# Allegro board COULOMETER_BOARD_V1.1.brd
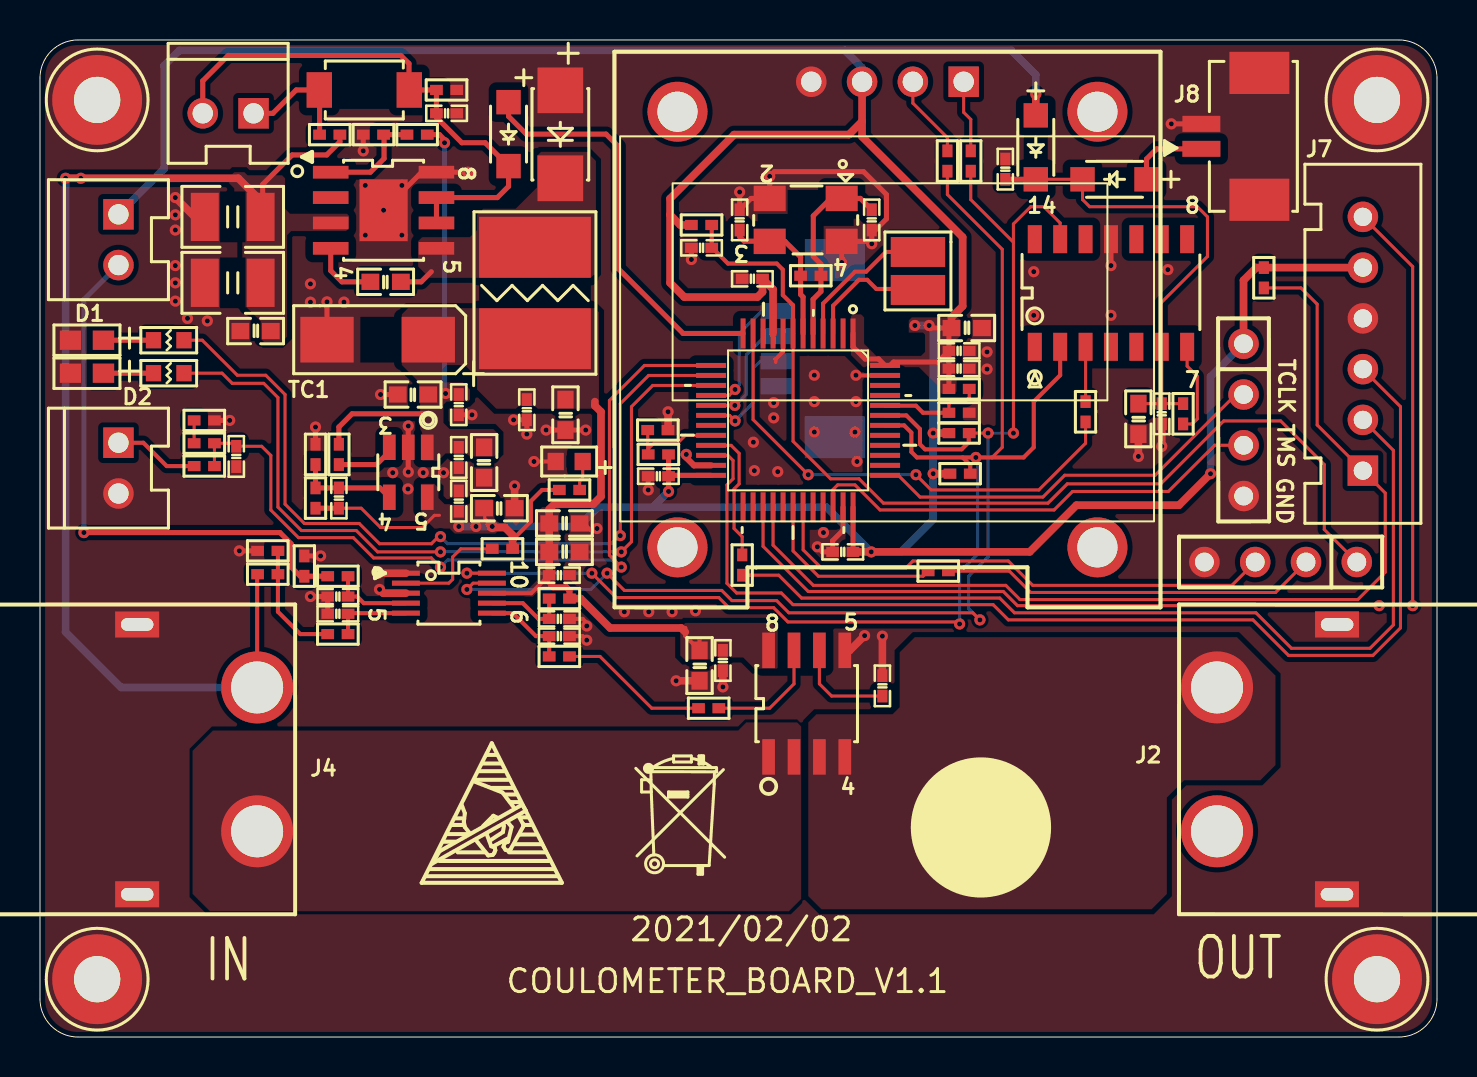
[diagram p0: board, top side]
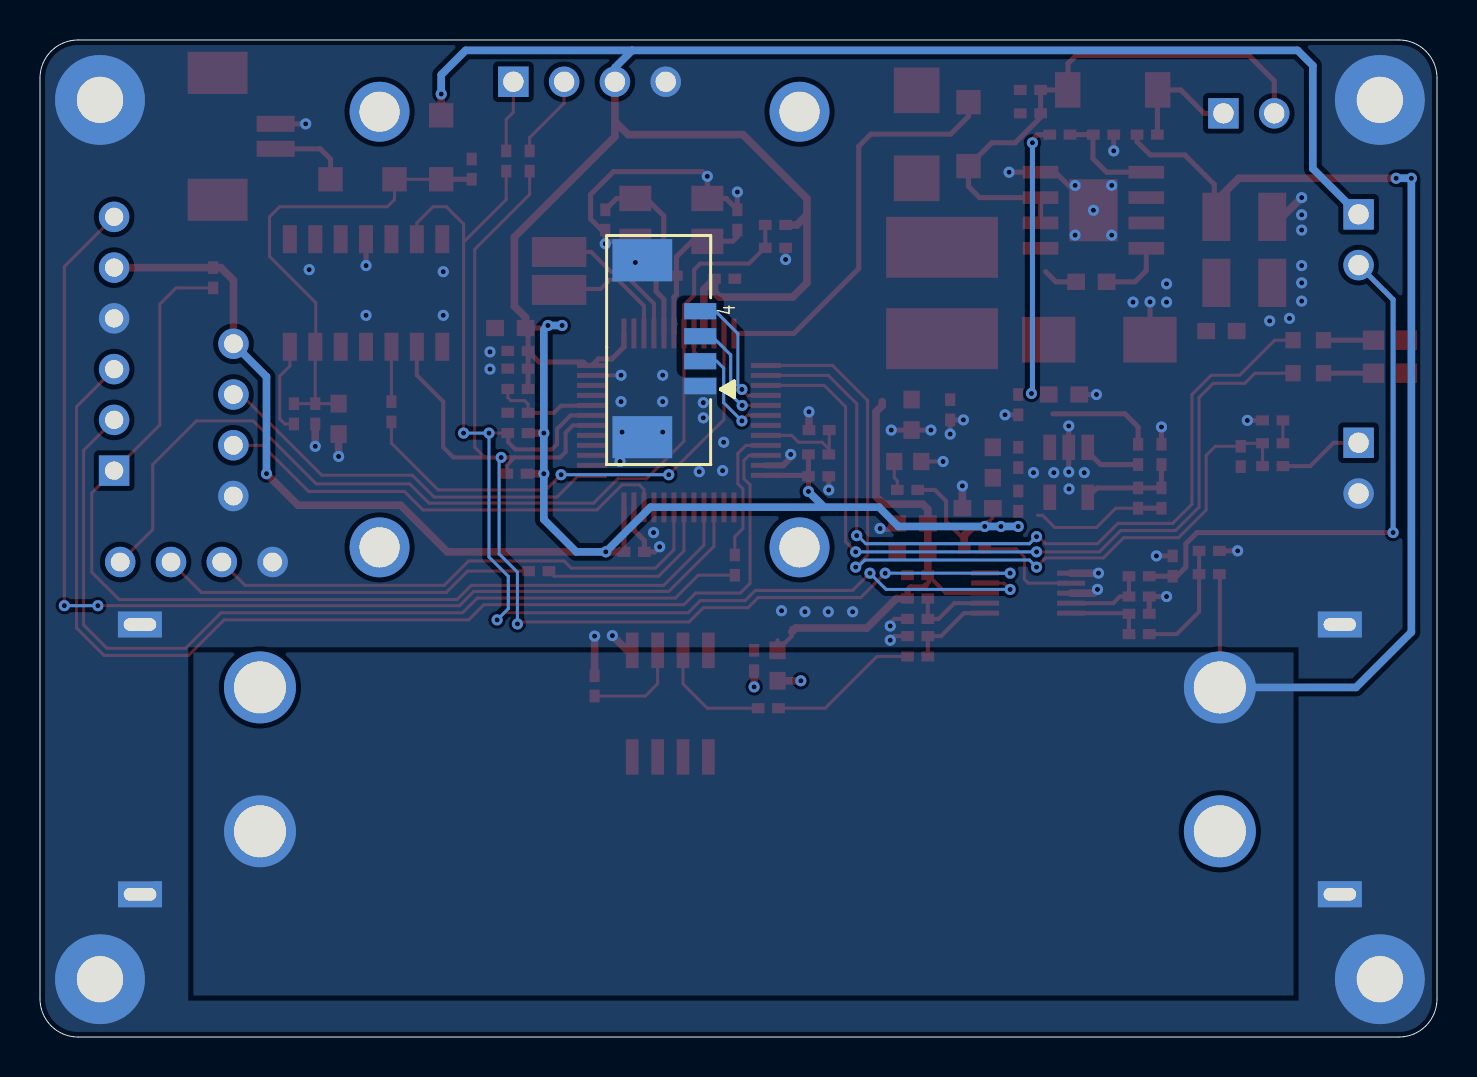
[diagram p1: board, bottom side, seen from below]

Outline 69.86 x 49.89 mm; copper layers: TOP, BOTTOM. Coordinates in mm from the lower left corner of the outline.
Outline path: 0,47.99 0,1.91 arc(0.56,0.56) 1.91,0 67.95,0 arc(69.3,0.56) 69.86,1.91 69.86,47.99 arc(69.3,49.34) 67.95,49.89 1.91,49.89 arc(0.56,49.34) 0,47.99

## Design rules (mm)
constraint set DEFAULT: min track width 0.152

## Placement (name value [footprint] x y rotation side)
C1  0.1uF/16V  [C0402]  33.08 39.49 180 top
C4  18pF/50V  [C0402]  34.99 40.89 270 top
C5  18pF/50V  [C0402]  41.59 40.89 90 top
C11  0.1uF/16V  [C0402]  35.62 37.94 180 top
C15  10uF/10V  [C0603]  46.34 35.48 180 top
C16  0.1uF/16V  [C0402]  40.14 24.28 180 top
C17  0.1uF/16V  [C0402]  45.96 34.34 0 top
C18  0.1uF/16V  [C0402]  45.96 33.45 0 top
C19  0.1uF/16V  [C0402]  30.92 28.06 180 top
C21  2.2uF/100V  [C1210]  9.64 41.04 0 top
C22  2.2uF/100V  [C1210]  9.64 37.74 0 top
C23  0.1uF/100V  [C0603]  10.78 35.33 180 top
C24  0.1uF/100V  [C0603]  17.28 37.79 0 top
C25  0.1uF/16V  [C0402]  20.94 31.64 270 top
C27  10uF/10V  [C0603]  18.65 32.15 0 top
C28  10uF/10V  [C0603]  26.27 31.14 90 top
C29  0.1uF/16V  [C0402]  24.34 31.39 270 top
C35  0.1uF/16V  [C0402]  20.33 46.22 0 top
C36  0.1uF/50V  [C0402]  34.15 18.84 270 top
C37  10uF/16V  [C0603]  32.98 18.59 90 top
C38  0.1uF/50V  [C0402]  42.12 17.57 90 top
C39  0.1uF/50V  [C0402]  25.97 23.11 0 top
C40  10uF/16V  [C0603]  26.22 25.7 180 top
C41  10uF/16V  [C0603]  26.22 24.28 180 top
C42  1nF/50V  [C0402]  14.9 21.18 180 top
C43  1nF/50V  [C0402]  14.9 22.04 180 top
C44  1nF/50V  [C0402]  25.97 20.93 0 top
C45  1nF/50V  [C0402]  25.97 20.06 0 top
C46  10uF/10V  [C0603]  54.93 30.93 90 top
C47  0.1uF/16V  [C0402]  56.09 31.19 270 top
C48  0.1uF/16V  [C0402]  48.27 43.43 90 top
C49  10uF/16V  [C0603]  22.97 26.46 0 top
C50  10uF/16V  [C0603]  22.21 28.75 270 top
C51  0.1uF/50V  [C0402]  20.94 29 270 top
C52  NC/1nF/50V  [C0402]  14.95 26.97 90 top
C53  0.1uF/50V  [C0402]  20.94 26.82 90 top
C54  1nF/50V  [C0402]  9.82 29.05 270 top
D1  Green  [D0603]  2.35 34.87 270 top
D2  Green  [D0603]  2.35 33.22 270 top
D18  MBRA340  [DO-214AC]  26.02 45.17 270 top
D19  IN4148  [SOD-123]  23.43 45.18 270 top
D20  IN4148  [SOD-123]  49.8 44.52 270 top
D21  IN4148  [SOD-123]  53.73 42.92 180 top
D22  Green  [D0603A]  26.46 28.8 180 top
J1  SIP4-100_180D_NC  [SIP_4P_100_42]  60.18 34.69 270.1 top
J2  XT60PW-M  [XT60PW]  61.86 13.89 270 top
J3  SIP4-100_180D_NC  [SIP_4P_100_42]  65.85 23.77 180 top
J4  XT60PW-F  [XT60PW]  7.86 13.89 90 top
J7  SIP_6P  [SIP6-100]  66.15 28.34 90 top
J8  -  [SMT_2PIN_1_25MM_180]  58.08 45.07 90 top
J9  SIP_2P_NC  [SIP2-100]  3.92 28.47 270 top
J10  SIP_2P_NC  [SIP2-100]  3.92 39.9 270 top
J11  SIP_2P_NC  [SIP2-100]  9.41 46.22 180 top
J12  -  [SMT_4PIN_1_25MM_90]  36.84 34.44 90 bottom
L1  33uH/1A  [PL0707]  24.75 37.23 270 top
MH1  M2-3  [M2-3_4-5]  2.86 2.89 0 top
MH2  M2-3  [M2-3_4-5]  66.86 2.89 0 top
MH3  M2-3  [M2-3_4-5]  66.86 46.89 0 top
MH4  M2-3  [M2-3_4-5]  2.86 46.89 0 top
NOREF  -  []  47.56 10.71 0 top
NOREF#2  -  []  23.28 10.71 180 bottom
NOREF#3  -  []  29.48 11.22 180 bottom
OLED1  OLED_SIP4-100  [OLED_SIP4-100_NEW]  42.38 35.4 0 top
R1  1K_1%  [R0402]  45.96 31.24 0 top
R2  4.7K_5%  [R0402]  45.96 30.22 180 top
R3  4.7K_5%  [R0402]  46.01 28.19 180 top
R4  1K_1%_NC  [R0402]  45.96 32.43 180 top
R5  4.7K_5%  [R0402]  33.08 40.64 0 top
R7  1K_1%_NC  [R0402]  30.92 29.15 0 top
R8  1K_1%  [R0402]  30.9 30.37 0 top
R9  1M_5%  [R0402]  38.54 38.1 180 top
R18  22R_5%  [R0402]  44.92 23.31 0 top
R27  330R_1%  [R0603]  6.44 34.87 0 top
R28  330R_1%  [R0603]  6.44 33.22 0 top
R29  22R_5%  [R0402]  35.11 23.62 270 top
R31  100K_1%  [R0402]  14.49 45.16 180 top
R32  22R_5%  [R0402]  46.54 43.84 270 top
R33  22R_5%  [R0402]  45.38 43.84 270 top
R34  4.7K_5%  [R0402]  20.33 47.39 0 top
R35  237K_1%  [R0402]  18.86 45.16 0 top
R36  10K_1%  [R0402]  16.67 45.16 180 top
R40  10K_1%  [R0402]  61.2 37.99 90 top
R41  1K_1%  [R0402]  8.22 29.71 180 top
R42  1K_1%  [R0402]  8.22 28.57 0 top
R43  1K_1%  [R0402]  8.22 30.86 0 top
R44  10K_1%  [R0402]  13.22 23.57 270 top
R47  22R_5%  [R0402]  33.44 16.45 180 top
R48  10K_1%  [R0402]  23.13 24.43 0 top
R51  1K_1%  [R0402]  14.9 23.06 0 top
R52  1K_1%  [R0402]  25.97 21.94 180 top
R53  1K_1%  [R0402]  14.9 20.16 0 top
R54  1K_1%  [R0402]  25.97 19.05 180 top
R57  22R_5%  [R0402]  52.28 31.29 90 top
R58  1K_1%  [R0402]  57.16 31.19 270 top
R59  100K_1%  [R0402]  14.95 29.15 270 top
R60  15K_1%  [R0402]  13.78 26.97 270 top
R61  1K_1%  [R0402]  26.48 27.38 180 top
R62  4.7K_1%  [R0402]  13.78 29.15 270 top
R63  100K_1%  [R0402]  11.39 23.16 0 top
R64  4.7K_1%  [R0402]  11.39 24.33 180 top
SW1  -  [KEY-2-180]  16.22 47.39 180 top
TC1  100uF/10V  [SMD_C6-3]  16.88 34.9 180 top
U2  STM32F103C8T6  [LQFP48]  37.91 30.86 180 top
U4  MP9485  [HSOP-8-PAD]  17.18 41.37 270 top
U5  ACS724  [SOP8-50-150]  38.34 16.68 0 top
U6  ADS1015IDGST  [VSSOP10]  20.45 22.21 270 top
U7  RX-8025  [SOP-14]  53.55 37.23 0 top
U8  AP2127K-ADJTRG1  [SOT23-5]  18.42 28.26 180 top
Y1  8MHz  [X4-0503]  38.29 40.89 180 top
Y2  32.768KHZ  [XTAL_HSX2-3225]  43.9 38.33 90 top

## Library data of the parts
C1 C11 = CAP
C4 C5 = CAP NP_3
C15 C21 C22 C27 C28 C37 C40 C41 C46 = 0_2.1uF Chip Cap
C16-C19 C23-C25 C29 C35 C36 C38 C39 C42-C45 C47 C48 C54 = CAP NP
C49-C53 = C
D1 D2 D22 = LED Green/TH
D18 = MA10702/TO_2
D19-D21 = MA10702/TO_0
J1 J3 = CONN PWR 4-R_0
J2 J4 = CONN PWR 4-R_3
J7 = SIP_0
J8 = SMT_2PIN_0-8MM
J9-J11 = SIP_1
J12 = SMT_2PIN_0: User Part Number: PART
L1 = INDUCTOR_0
MH1-MH4 = M2-7
OLED1 = CONN PWR 4-R_5
R1 R4 R7 R8 = R_4
R2 R3 R5 R27 R28 R31-R36 R40-R44 R47 R57 R58 R63 R64 = R_2
R9 R18 R29 R48 R51-R54 = R
R59 R60 R62 = R_1
R61 = R_10
SW1 = KEY-2PIN_0
TC1 = CAP P_0
U2 = STM32F103C8T6
U4 = TPS63700_2
U5 = ACS724_0
U6 = ADS1015_0
U7 = RX8025
U8 = ADP122_123
Y1 = CRYSTAL 4-PIN_1
Y2 = X_1

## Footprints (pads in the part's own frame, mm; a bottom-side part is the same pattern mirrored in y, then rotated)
C0402
  rect 0.635x0.508 smd: 1(-0.508,0) 2(0.508,0)
C0603
  rect 0.889x0.813 smd: 1(-0.762,0) 2(0.762,0)
C1210
  rect 1.397x2.413 smd: 1(-1.397,0) 2(1.397,0)
D0603
  rect 0.965x1.067 smd: 1(0,0.826) 2(0,-0.826)
D0603A
  rect 0.813x0.864 smd: 1(-0.675,0) 2(0.675,0)
DO-214AC
  rect 2.286x2.286 smd: 1(2.2,0) 2(-2.2,0)
HSOP-8-PAD
  rect 0.635x1.778 smd: 1(-1.905,-2.644) 2(-0.635,-2.644) 3(0.635,-2.644) 4(1.905,-2.644) 5(1.905,2.644) 6(0.635,2.644) 7(-0.635,2.644) 8(-1.905,2.644)
  rect 3.099x2.413 smd: 9(0,0)
KEY-2-180
  rect 1.27x1.778 smd: 1(-2.25,0) 2(2.25,0)
LQFP48
  rect 0.25x1.5 smd: 1(-2.75,-4.35) 2(-2.25,-4.35) 3(-1.75,-4.35) 4(-1.25,-4.35) 5(-0.75,-4.35) 6(-0.25,-4.35) 7(0.25,-4.35) 8(0.75,-4.35) 9(1.25,-4.35) 10(1.75,-4.35) 11(2.25,-4.35) 12(2.75,-4.35) 25(2.75,4.35) 26(2.25,4.35) 27(1.75,4.35) 28(1.25,4.35) 29(0.75,4.35) 30(0.25,4.35) 31(-0.25,4.35) 32(-0.75,4.35) 33(-1.25,4.35) 34(-1.75,4.35) 35(-2.25,4.35) 36(-2.75,4.35)
  rect 1.5x0.25 smd: 13(4.35,-2.75) 14(4.35,-2.25) 15(4.35,-1.75) 16(4.35,-1.25) 17(4.35,-0.75) 18(4.35,-0.25) 19(4.35,0.25) 20(4.35,0.75) 21(4.35,1.25) 22(4.35,1.75) 23(4.35,2.25) 24(4.35,2.75) 37(-4.35,2.75) 38(-4.35,2.25) 39(-4.35,1.75) 40(-4.35,1.25) 41(-4.35,0.75) 42(-4.35,0.25) 43(-4.35,-0.25) 44(-4.35,-0.75) 45(-4.35,-1.25) 46(-4.35,-1.75) 47(-4.35,-2.25) 48(-4.35,-2.75)
M2-3_4-5
  round 4.496 hole 2.311: 1(0,0)
OLED_SIP4-100_NEW
  round 2.997 hole 2.007: (-10.5,10.9) (-10.5,-10.9) (10.5,10.9) (10.5,-10.9)
  round 1.524 hole 1.016: 1(-3.81,12.4) 2(-1.27,12.4) 3(1.27,12.4)
  rect 1.524x1.524 hole 1.016: 4(3.81,12.4)
PL0707
  rect 3.048x5.588 smd: 1(-2.286,0) 2(2.286,0)
R0402
  rect 0.635x0.508 smd: 1(-0.508,0) 2(0.508,0)
R0603
  rect 0.762x0.813 smd: 1(-0.762,0) 2(0.762,0)
SIP2-100
  rect 1.524x1.524 hole 1.016: 1(-1.27,0)
  round 1.524 hole 1.016: 2(1.27,0)
SIP6-100
  rect 1.524x1.524 hole 0.914: 1(0,0)
  round 1.524 hole 0.914: 2(2.54,0) 3(5.08,0) 4(7.62,0) 5(10.16,0) 6(12.7,0)
SIP_4P_100_42
  round 1.524 hole 0.94: 1(0,0) 2(2.54,0) 3(5.08,0) 4(7.62,0)
SMD_C6-3
  rect 2.667x2.286 smd: 1(-2.533,0) 2(2.533,0)
SMT_2PIN_1_25MM_180
  rect 0.8x1.9 smd: 1(-0.625,0) 2(0.625,0)
  rect 2.108x2.997 smd: 3(-3.175,-2.9) 4(3.175,-2.9)
SMT_4PIN_1_25MM_90
  rect 0.813x1.6 smd: 1(-1.87,0) 2(-0.62,0) 3(0.63,0) 4(1.88,0)
  rect 2.108x2.997 smd: 5(4.43,2.9) 6(-4.42,2.9)
SOD-123
  rect 1.219x1.219 smd: 1(-1.6,0) 2(1.6,0)
SOP8-50-150
  rect 0.635x1.778 smd: 1(-1.905,-2.667) 2(-0.635,-2.667) 3(0.635,-2.667) 4(1.905,-2.667) 5(1.905,2.667) 6(0.635,2.667) 7(-0.635,2.667) 8(-1.905,2.667)
SOP-14
  rect 0.7x1.4 smd: 1(-3.81,-2.692) 2(-2.54,-2.692) 3(-1.27,-2.692) 4(0,-2.692) 5(1.27,-2.692) 6(2.54,-2.692) 7(3.81,-2.692) 8(3.81,2.692) 9(2.54,2.692) 10(1.27,2.692) 11(0,2.692) 12(-1.27,2.692) 13(-2.54,2.692) 14(-3.81,2.692)
SOT23-5
  rect 0.635x1.27 smd: 1(-0.95,-1.25) 2(0,-1.25) 3(0.95,-1.25) 4(0.95,1.25) 5(-0.95,1.25)
VSSOP10
  rect 0.254x1.397 smd: 1(-1,-2.15) 2(-0.5,-2.15) 3(0,-2.15) 4(0.5,-2.15) 5(1,-2.15) 6(1,2.15) 7(0.5,2.15) 8(0,2.15) 9(-0.5,2.15) 10(-1,2.15)
X4-0503
  rect 1.6x1.27 smd: 1(-1.8,-1.075) 2(1.8,-1.075) 3(1.8,1.075) 4(-1.8,1.075)
XT60PW
  round 3.6 hole 2.6: 1(3.6,-3) 2(-3.6,-3)
  rect 1.3x2.2 hole 0.635x1.626: 3(6.75,3) 4(-6.75,3)
XTAL_HSX2-3225
  rect 1.499x2.718 smd: 1(-0.95,0) 2(0.95,0)

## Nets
GND: C1.2 C4.1 C5.1 C11.2 C15.1 C16.2 C17.2 C18.2 C19.2 C21.1 C22.1 C23.2 C25.2 C27.1 C28.1 C29.2 C35.2 C36.2 C37.1 C38.2 C39.2 C40.1 C41.1 C42.2 C43.2 C44.2 C45.2 C46.1 C47.2 C48.2 C49.2(B) C50.2(B) C51.2(B) C53.2(B) C54.2 D1.2(C) D2.2(C) D18.2 D22.2(C) J1.4 J2.3 J2.4 J3.4 J4.2 J4.3 J4.4 J7.4 J8.2 J8.3 J8.4 J9.2 J12.1 J12.5 J12.6 MH1.1 MH2.1 MH3.1 MH4.1 OLED1.1 R1.2 R8.2 R34.2 R36.2 R43.2 R44.1 R62.1 R64.2 TC1.2 U2.8 U2.23 U2.35 U2.47(VSS_3) U4.8 U4.9 U5.1 U5.2 U5.5 U6.1 U6.3 U7.11 U8.2 Y1.2 Y1.4
VCC_3V3: C11.1 C15.2 C16.1 C17.1 C18.1 C19.1 C49.1 C52.1 C53.1 D20.1 J1.1 J7.5 J10.1 OLED1.2 R2.2 R3.2 R4.2 R5.1 R7.2 R40.2 R48.2 R60.2(B) R61.2(B) U2.1 U2.9 U2.24 U2.36 U2.48 U8.5(VOUT)
VCC_5V: C25.1 C27.2 C28.2 C29.1 C36.1 C37.2 C39.1 C40.2 C41.2 C50.1 C51.1 L1.2 R35.2 R52.1 R59.1 TC1.1 U5.8 U6.8(VDD) U8.1
VCC_BAT: D21.1 J8.1
VCC_IN: C21.2 C22.2 C23.1 J2.1 J4.1 R31.1 R63.1 U4.3(VIN)
VCC_RTC: C46.2 C47.1 C48.1 D20.2(CATHODE) D21.2(CATHODE) R58.1 U7.6(VDD)
ADC_ALERT: R48.1 U6.2
ADC_CURRENT: R47.2 R54.1
ADC_NTC: J10.2 R44.2 R51.1
ADC_VOLTAGE: R53.1 R63.2 R64.1
ARM_RESET: C1.1 J3.1 R5.2 U2.7
BOOT0: R1.1 R4.1 U2.44
BOOT1: R7.1 R8.1 U2.20
BT_EN: J7.6 U2.27
BT_STATE: J7.1 R40.1 U2.28
BT_UART_RXD: J7.3 U2.22
BT_UART_TXD: J7.2 R29.2
FOUT: R57.1 U2.11
HALL_IN: C54.1 R41.1 R42.2 U2.13
KEY_DOWN: J12.4 U2.16
KEY_MODE: J12.2 U2.18
KEY_UP: J12.3 U2.17
RTC_OSC_IN: U2.3 Y2.1
RTC_OSC_OUT: U2.4 Y2.2
SAMPLE_CURRENT: J2.2 U5.3 U5.4
STM32_IIC_SCL: R3.1 R33.2 U2.42 U6.10 U7.2
STM32_IIC_SDA: R2.1 R32.2 U2.43 U6.9 U7.13
STM32_RXD: J3.3 U2.31
STM32_TXD: J3.2 R18.2
SWCLK: J1.2 U2.37
SWIO: J1.3 U2.34
SYS_OSC_IN: C5.2 R9.1 U2.5 Y1.1(Y1)
SYS_OSC_OUT: C4.2 R9.2 U2.6 Y1.3
SYS_POWER_EN: D19.1 U2.12
N17137389: R18.1 U2.30
N17151431: R29.1 U2.21
N17159522: C35.1 D19.2(CATHODE) J11.2 R34.1 SW1.1 U4.6 U4.7
N17161102: C24.1 U4.4
N17161105: C24.2 D18.1(CATHODE) L1.1 U4.5
N17161689: R35.1 R36.1 U4.1
N17168849: D1.1 R27.1
N17168859: D2.1 R28.1
N17169618: R27.2 U2.14
N17169623: R28.2 U2.15
N17176733: J9.1 R42.1
N17176975: R41.2 R43.1
N17186713: J11.1 R31.2 SW1.2
N17198791: OLED1.3 R33.1
N17198794: OLED1.4 R32.1
N17215392: C45.1 R54.2 U6.6
N17215498: C43.1 R51.2 U6.4
N17215508: C42.1 R53.2 U6.5
N17220729: R47.1 U5.7(VIOUT)
N17220953: C38.1 U5.6
N17223356: C44.1 R52.2 U6.7
N17230489: C52.2(B) R60.1 R62.2(B) U8.4
N17230525: R59.2(B) U8.3
N17230626: D22.1 R61.1
N17243139: R58.2 U7.7
N17243155: R57.2 U7.3

Pads without a net: U2 2 10 19 25 26 29 32 33 38 39 40 41 45 46; U4 2; U7 1 4 5 8 9 10 12 14

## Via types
v1: diameter 0.559, hole 0.254, TOP to BOTTOM, 121 vias

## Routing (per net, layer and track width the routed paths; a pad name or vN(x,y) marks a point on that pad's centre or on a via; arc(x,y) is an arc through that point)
GND: length 66
  TOP w0.203: 26.99,25.9 27.5,25.39 27.79,25.39 v1(27.85,25.45) ; v1(40.8,33.12) 40.81,33.11 U2.47 ; C44.2 27.14,20.93 27.34,20.72 v1(27.34,20.57) ; 36.79,33.78 36.79,33.93 37.16,34.3 U2.8 ; D22.2 v1(24.7,28.8) ; v1(27.34,19.86) 27.14,20.06 C45.2
  TOP w0.254: R36.2 v1(16.17,44.34) ; v1(13.52,22.04) C43.2 C42.2 ; v1(25.31,30.37) C28.1 v1(27.29,30.37) ; v1(38.87,24.53) 39.13,24.28 C16.2 39.64,24.84 40.16,25.36 U2.35 ; v1(21.4,43.28) U4.8 19.09,43.28 v1(17.18,41.37) ; TC1.2 v1(14.35,36.79) ; R43.2 v1(9.49,30.86) ; C19.2 v1(30.42,27.38) ; R64.2 v1(9.97,24.33) ; v1(23.68,30.88) C29.2 v1(24.34,30.17) ; v1(34.99,42.29) C4.1 35.55,41.96 Y1.2 v1(36.49,43.07) 36.72,43.3 41.18,43.3 42.33,42.16 42.33,40.94 41.77,40.38 C5.1 v1(41.59,39.7) 41.47,39.81 Y1.4 v1(40.09,38.76) ; R44.1 v1(14.03,24.07) ; U7.11 v1(53.55,38.6) ; v1(18.42,28.28) U8.2 v1(18.42,30.58) ; C1.2 v1(32.57,38.91) ; R62.1 v1(13.78,30.53) ; C25.2 v1(21.6,31.14) ; C27.1 v1(17.03,32.15) ; J8.2 v1(56.57,45.7)
  TOP w0.305: v1(32.32,29.15) 32.32,28.99 32.7,28.61 U2.23
  TOP w0.381: U5.5 40.5,19.35 v1(41.24,20.09) ; C37.1 v1(31.81,17.83) ; R8.2 v1(31.41,31.29) ; C38.2 v1(42.12,20.06) ; C36.2 v1(34.15,17.52) ; U6.3 17.17,22.21 v1(16.98,22.4) ; C49.2 v1(23.73,27.58) ; C47.2 v1(56.09,29.56) ; U6.1 v1(16.93,23.21) ; C21.1 7.73,41.04 v1(6.77,42.01) ; C46.1 v1(54.93,29.05)
  vias: v1(6.77,41.14) v1(6.77,40.38) v1(6.77,38.6) v1(6.77,37.74) v1(6.77,36.83) v1(7.38,35.96) v1(8.37,35.84) v1(13.52,37.69) v1(13.52,36.77) v1(15.2,36.77) v1(16.27,42.62) v1(16.27,40.13) v1(17.64,28.24) v1(18.1,42.62) v1(18.1,40.13) v1(18.4,27.43) v1(19.16,28.24) v1(20.18,28.24) v1(29.22,21.28) v1(30.44,21.28) v1(31.61,21.28) v1(32.78,21.33) v1(35.67,29.76) v1(35.72,28.34) v1(36.69,31.75) v1(36.69,30.98) v1(36.89,28.29) v1(38.72,33.12) v1(38.72,31.8) v1(38.72,30.27) v1(39.18,25.24) v1(40.8,31.8) v1(40.75,30.27) v1(40.85,28.8) v1(47.36,34.29) v1(47.36,33.42) v1(49.69,38.3) v1(49.69,36.11) v1(53.55,36.11) v1(56.4,38.4)
VCC_3V3: length 202.2
  TOP w0.152: C49.1 22.24,26.44 22.24,25.95 22.46,25.73 22.46,25.7 ; 19.98,26.11 19.72,26.11 19.11,25.5 17.03,25.5 16.06,26.46 C52.1
  TOP w0.203: R61.2 25.11,27.38 24.55,26.82 24.55,25.8 23.63,24.89
  TOP w0.254: U2.36 40.66,24.28 C16.1 ; U2.1 40.66,34.53 41.26,33.93 41.93,33.93 U2.48 42.51,33.61 42.68,33.78 44.89,33.78 C17.1 ; R60.2 C52.1 ; C19.1 v1(31.43,27.3) ; C19.1 R7.2 ; C19.1 31.47,28.11 U2.24 ; C17.1 C18.1 R4.2 ; C17.1 45.45,35.35 C15.2 44.59,35.48 v1(44.46,35.61)
  TOP w0.381: OLED1.2 41.11,45.82 ; 41.11,45.82 40.45,45.16 34.71,45.16 31.51,41.96 31.51,41.14 ; 41.11,45.82 41.11,45.06 46.14,40.03 46.14,36.57 45.58,36.01 C15.2 ; 31.51,41.14 32.02,40.64 R5.1 ; 31.51,41.14 31.51,37.74 32.22,37.03 35.88,37.03 36.13,37.28 C11.1 36.66,37.42 U2.9 ; C16.1 v1(41.57,24.28) 49.49,24.28 51.83,26.61 56.96,26.61 v1(58.53,28.19) ; J1.1 60.18,37.87 60.82,38.5 R40.2 J7.5 ; 22.46,25.7 v1(22.62,25.55) 22.67,25.5 23.25,25.5 23.63,25.12 R48.2 ; D20.1 v1(49.8,47.19) ; R2.2 v1(44.66,30.22) ; R3.2 v1(44.66,28.19)
  BOTTOM w0.381: v1(58.53,28.19) 58.53,33.04 J1.1 ; J10.1 6.21,43.46 6.21,48.61 6.97,49.37 40.24,49.37 ; 30.64,26.51 27.9,26.51 26.94,25.55 v1(22.62,25.55) v1(21.8,25.55) v1(20.94,25.55) ; 30.64,26.51 v1(31.43,27.3) ; 30.64,26.51 39.33,26.51 v1(41.57,24.28) 43.04,24.28 44.66,25.9 v1(44.66,28.19) v1(44.66,30.22) 44.66,35.4 v1(44.46,35.61) v1(43.75,35.61) ; OLED1.2 41.11,48.51 40.24,49.37 ; 40.24,49.37 48.58,49.37 49.8,48.15 v1(49.8,47.19)
VCC_5V: length 43.9
  TOP w0.203: 25.56,22.6 25.42,22.75 25.42,23.07 ; 25.42,23.07 C39.1 ; 25.42,23.07 24.56,22.21 U6.8 ; 32.98,19.86 C37.2 32.27,20.06 32.27,20.47 32.07,20.47
  TOP w0.254: v1(20.23,44.75) 20.23,44.9 19.98,45.16 R35.2 ; R59.1 14.95,30.53 15.61,31.19 19.21,31.19
  TOP w0.305: R52.1 26.48,22.35 26.33,22.5 25.67,22.5 25.56,22.6
  TOP w0.381: R52.1 27.04,21.94 28.51,20.47 32.07,20.47 32.27,20.26 ; C39.1 C41.2 C40.2 25.46,26.41 25.72,26.67 27.67,26.67 28.05,27.05 28.05,31.29 27.75,31.59 27.75,31.8
  BOTTOM w0.254: v1(20.28,32.2) 20.23,32.25 v1(20.23,44.75)
VCC_BAT: length 4
  TOP w0.254: D21.1 55.33,43.94 55.84,44.45 J8.1
VCC_IN: length 57.7
  TOP w0.203: R63.1 10.86,23.14 J4.1
  TOP w0.254: C21.2 11.14,41.14 11.14,42.67 12.61,44.14 14.34,44.14 15,44.8 R31.1
  TOP w0.381: v1(1.28,42.97) v1(2.04,42.97) 9.92,42.97 11.03,41.85 C21.2
  BOTTOM w0.381: v1(2.04,42.97) v1(1.28,42.97) 1.28,20.26 4.05,17.49 J4.1
VCC_RTC: length 24
  TOP w0.152: D20.2 D21.2 52.13,41.91 52.49,41.55 57.87,41.55 58.38,41.04 58.38,39.06 56.07,36.75 56.07,34.57 U7.6 C47.1 ; C47.1 R58.1 ; C47.1 C46.2
  TOP w0.254: C48.1 D20.2
ADC_ALERT: length 5.7
  TOP w0.152: U6.2 20.44,22.71 20.64,22.91 20.64,24.02 21.04,24.43 R48.1
ADC_CURRENT: length 7.5
  TOP w0.152: R47.2 30.59,16.45 28,19.05 R54.1
ADC_NTC: length 27.9
  TOP w0.254: v1(2.2,25.24) 12,25.24 12.56,24.68 12.56,23.52 13.02,23.06 R44.2 R51.1
  BOTTOM w0.254: v1(2.2,25.24) 2.2,36.9 J10.2
ADC_VOLTAGE: length 6
  TOP w0.203: R64.1 R63.2 11.9,21.28 13.02,20.16 R53.1
ARM_RESET: length 50
  TOP w0.152: J3.1 64.22,25.4 64.22,28.65 62.04,30.83 59.19,30.83 56.04,27.68 51.37,27.68 50.4,26.72 42.18,26.72 40.96,27.94 39.53,27.94 37.66,29.81 U2.7
  TOP w0.203: U2.7 37.65,35.21 37.65,36.62 37.15,37.13 37.15,38.4 36.84,38.71 34.4,38.71 33.62,39.49 C1.1 R5.2
BOOT0: length 5.4
  TOP w0.152: R4.1 46.47,32 46.32,31.85 45.63,31.85 45.45,31.67 R1.1
  TOP w0.203: R1.1 44.16,31.24 43.8,31.59 42.27,31.59 U2.44
BOOT1: length 4.9
  TOP w0.152: R8.1 30.39,29.18 R7.1 30.42,29.43 30.75,29.76 31.93,29.76 32.27,30.11 U2.20
BT_EN: length 56.2
  TOP w0.152: v1(66.97,21.59) 48.88,21.59 48.17,22.3 38.42,22.3 36.16,24.55 U2.27 ; J7.6 68.64,38.55 v1(68.64,21.59)
  BOTTOM w0.152: v1(66.97,21.59) v1(68.64,21.59)
BT_STATE: length 52
  TOP w0.152: U2.28 36.66,24.61 38.67,22.6 48.3,22.6 49.01,21.89 65.9,21.89 67.27,23.26 67.27,27.22 J7.1 63.87,30.63 63.87,36.67 63.05,37.49 R40.1
BT_UART_RXD: length 57
  TOP w0.152: U2.22 34.4,29.11 34.66,28.85 34.66,27.94 34.35,27.63 34.35,22.7 34.83,22.22 37.07,22.22 37.65,21.64 47.66,21.64 48.42,20.87 60.66,20.87 62.43,19.1 66.66,19.1 68.03,20.47 68.03,31.54 J7.3
BT_UART_TXD: length 45.5
  TOP w0.152: J7.2 67.68,29.36 67.68,20.62 66.51,19.45 62.58,19.45 60.8,21.23 48.73,21.23 47.99,21.97 38.09,21.97 36.94,23.11 R29.2
FOUT: length 24.4
  TOP w0.152: v1(38.42,28.14) 35.66,30.9 U2.11 ; R57.1 52.28,29.71 49.95,27.38 44.56,27.38 v1(43.8,28.14)
  BOTTOM w0.152: v1(38.42,28.14) v1(43.8,28.14)
HALL_IN: length 40.3
  TOP w0.152: v1(20.03,23.52) 19.57,23.97 16.68,23.97 15.67,24.99 12.92,24.99 11.54,26.37 11.54,29.1 11.09,29.56 C54.1 9.66,29.71 R41.1 R42.2 ; U2.13 30.23,33.61 28.48,31.86 28.48,24.11 v1(29.07,23.52)
  BOTTOM w0.152: v1(20.03,23.52) 20.38,23.87 28.61,23.87 28.97,23.52 v1(29.07,23.52)
KEY_DOWN: length 6.5
  TOP w0.152: v1(34.76,32.41) 34.46,32.11 U2.16
  BOTTOM w0.152: J12.4 36.08,36.32 34.96,35.2 34.96,32.61 v1(34.76,32.41)
KEY_MODE: length 5.6
  TOP w0.152: U2.18 34.48,31.11 v1(34.76,30.83)
  BOTTOM w0.152: J12.2 36.02,33.82 35.67,33.47 35.67,31.75 v1(34.76,30.83)
KEY_UP: length 5.9
  TOP w0.152: U2.17 v1(34.75,31.61)
  BOTTOM w0.152: v1(34.75,31.61) 34.77,31.61 35.32,32.15 35.32,34.13 36.25,35.07 J12.3
RTC_OSC_IN: length 6.4
  TOP w0.203: Y2.1 43.85,37.44 41.82,37.44 41.36,37.89 40.96,37.89 39.66,36.59 U2.3
RTC_OSC_OUT: length 7.3
  TOP w0.203: Y2.2 42.3,39.28 41.31,38.3 40.75,38.3 39.16,36.7 U2.4
STM32_IIC_SCL: length 66.8
  TOP w0.152: v1(45.99,20.67) 45.88,20.77 37.4,20.77 36.69,21.48 34.45,21.48 33.95,21.99 28.81,21.99 v1(27.6,23.21) ; R33.2 45.38,42.16 48.12,39.42 48.12,29.51 47.61,29 ; v1(21.35,23.21) U6.10
  TOP w0.203: R3.1 46.52,28.62 46.14,29 ; 46.14,29 43.85,29 43.57,29.28 43.57,30.25 43.21,30.61 U2.42 ; 46.14,29 v1(46.8,29) 49.19,29 49.69,29.51 49.69,31.8 51.01,33.12 U7.2
  BOTTOM w0.152: v1(21.35,23.21) v1(27.6,23.21) ; v1(45.99,20.67) 45.99,23.26 46.9,24.18 46.9,28.9 v1(46.8,29)
STM32_IIC_SDA: length 65.2
  TOP w0.152: U7.13 51.01,40.74 50.2,41.55 49.54,41.55 48.68,40.69 48.68,39.77 ; U6.9 21.66,22.71 v1(21.35,22.4) ; 48.68,39.77 46.54,41.91 R32.2 ; 48.68,39.77 v1(48.68,30.22) ; v1(47.41,30.22) R2.1 ; v1(47,20.87) 46.65,21.23 37.45,21.23 36.84,21.84 34.6,21.84 34.09,22.35 29.22,22.35 v1(28.36,23.21)
  TOP w0.203: R2.1 46.44,30.2 46.44,29.76 46.09,29.41 44.26,29.41 44,29.66 44,30.42 43.32,31.11 U2.43
  BOTTOM w0.152: v1(47,20.87) 46.44,21.43 46.44,23.06 47.41,24.02 v1(47.41,30.22) v1(48.68,30.22) ; v1(28.36,23.21) 27.54,22.4 v1(21.35,22.4)
STM32_RXD: length 26.2
  TOP w0.152: U2.31 38.16,26.5 38.16,24.38 39.08,23.47 43.29,23.47 43.65,23.82 48.42,23.82 49.64,22.6 59.6,22.6 J3.3
STM32_TXD: length 19
  TOP w0.152: R18.2 48.47,23.31 49.54,22.25 61.78,22.25 J3.2
SWCLK: length 20.5
  TOP w0.152: J1.2 59.8,32.15 55.76,28.11 51.24,28.11 50.15,27.02 44,27.02 42.92,28.11 U2.37
SWIO: length 23.4
  TOP w0.152: U2.34 39.66,27.4 39.89,27.63 40.75,27.63 42.01,26.38 50.71,26.38 51.63,27.3 56.42,27.3 58.74,29.61 J1.3
SYS_OSC_IN: length 9.7
  TOP w0.254: C5.2 41.02,41.96 Y1.1 39.54,41.96 38.67,41.09 38.67,39.06 39.05,38.68 R9.1 39.05,37.31 38.66,36.92 U2.5
SYS_OSC_OUT: length 7.7
  TOP w0.254: U2.6 38.16,37.03 38.04,37.16 R9.2 38.04,39.04 37.26,39.81 Y1.3 36.48,39.82 35.22,39.82 34.99,40.05 C4.2
SYS_POWER_EN: length 20.5
  TOP w0.254: U2.12 32.16,35.21 28.92,38.45 28.92,44.57 28.31,45.18 24.32,45.18 23.43,46.07 D19.1
N17137389: length 9.6
  TOP w0.152: U2.30 37.66,24.32 38.92,23.06 44.16,23.06 R18.1 44.46,23.26
N17151431: length 6.9
  TOP w0.152: R29.1 35.11,25.04 34.71,25.45 34.71,27.43 34.96,27.68 34.96,29.21 34.56,29.61 U2.21
N17159522: length 27.4
  TOP w0.254: J11.2 8.14,47.85 9.41,49.12 18.05,49.12 18.45,48.71 18.45,47.41 SW1.1 R34.1 C35.1 19.82,46.02 21.09,44.75 22.26,44.75 D19.2 23.43,42.57 22.87,42.01 U4.7 U4.6
N17161102: length 3.3
  TOP w0.254: U4.4 14.54,38.35 15.1,37.79 C24.1
N17161105: length 1.7
  TOP w0.254: 19.57,38.3 19.06,37.79 C24.2
N17161689: length 5.3
  TOP w0.254: R35.1 R36.1 17.21,45.13 17.21,43.96 16.52,43.28 U4.1
N17168849: length 2.5
  TOP w0.254: D1.1 R27.1
N17168859: length 2.5
  TOP w0.254: D2.1 R28.1
N17169618: length 41.4
  TOP w0.152: U2.14 30.43,33.11 29.02,31.69 v1(29.02,25.09) ; v1(20.03,25.04) 19.92,25.04 19.57,24.68 16.98,24.68 15.96,25.7 13.22,25.7 12.25,26.67 12.25,32.15 11.29,33.12 9.87,33.12 8.11,34.87 R27.2
  BOTTOM w0.152: v1(29.02,25.09) 28.97,25.09 28.56,24.68 20.38,24.68 v1(20.03,25.04)
N17169623: length 40.7
  TOP w0.152: v1(20.03,24.28) 16.88,24.28 15.82,25.34 13.07,25.34 11.9,26.52 11.9,32 11.19,32.71 9.61,32.71 9.1,33.22 R28.2 ; v1(29.07,24.28) 29.58,24.79 29.58,31.54 30.64,32.61 U2.15
  BOTTOM w0.152: v1(29.07,24.28) v1(20.03,24.28)
N17176733: length 4.3
  TOP w0.203: J9.1 5.17,29.74 6.34,28.57 R42.1
N17176975: length 1.1
  TOP w0.152: R41.2 R43.1
N17186713: length 6
  TOP w0.254: J11.1 11.64,46.22 12.81,47.39 SW1.2 13.98,47.38 R31.2
N17198791: length 4.2
  TOP w0.152: R33.1 45.38,45 43.65,46.73 OLED1.3
N17198794: length 3.6
  TOP w0.152: R32.1 46.54,45.92 46.19,46.27 OLED1.4
N17215392: length 4.4
  TOP w0.203: R54.2 C45.1 24.8,20.06 23.65,21.21 U6.6
N17215498: length 4
  TOP w0.203: U6.4 16.19,21.71 15.86,22.04 C43.1 R51.2
N17215508: length 3.9
  TOP w0.203: R53.2 C42.1 15.44,21.21 U6.5
N17220729: length 5.9
  TOP w0.152: R47.1 36.49,16.45 37.7,17.67 U5.7
N17220953: length 5.1
  TOP w0.152: C38.1 39.58,17.06 38.97,17.67 U5.6
N17223356: length 4.2
  TOP w0.203: R52.2 C44.1 24.93,20.93 24.14,21.71 U6.7
N17230489: length 5.1
  TOP w0.254: R62.2 R60.1 C52.2 17,27.48 U8.4
N17230525: length 3
  TOP w0.254: R59.2 16.83,28.65 17.47,29.29 U8.3
N17230626: length 1.5
  TOP w0.152: D22.1 27.14,27.99 26.99,27.83 R61.1
N17243139: length 4.6
  TOP w0.152: R58.2 57.62,30.68 57.87,30.93 57.87,33.07 57.36,33.57 U7.7
N17243155: length 2.7
  TOP w0.152: R57.2 U7.3

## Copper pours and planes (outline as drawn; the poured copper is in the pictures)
GND on TOP: 10.37,34.9 8.7,34.9 7.94,35.66 6.72,35.66 6.46,35.91 6.46,42.31 6.72,42.57 8.65,42.57 8.95,42.26 8.95,36.47 9.46,35.96 10.32,35.96 10.48,35.81 10.48,35
GND on TOP: 40.04,25.85 40.04,25.7 39.89,25.55 38.67,25.55 38.52,25.4 38.52,24.48 39.13,23.87 39.89,23.87 39.99,23.97 39.99,24.79 40.3,25.09 40.3,25.85
GND on TOP: -2.83,52.12 -2.83,0.66 0.21,-2.39 68.34,-2.39 74.84,4.11 74.84,45.87 67.22,53.49 -1.46,53.49 ; 23 cut-outs
GND on TOP: 12.71,33.42 12.71,37.84 13.02,38.15 14.03,38.15 14.79,37.38 15.51,37.38 15.76,37.13 15.76,33.37 15.61,33.22 12.91,33.22
GND on TOP: 18.1,30.73 18.1,28.85 17.89,28.65 17.49,28.65 17.33,28.49 17.33,27.99 17.54,27.78 17.94,27.78 18.05,27.68 18.05,27.22 18.2,27.07 18.65,27.07 18.86,27.28 18.86,27.68 19.01,27.83 19.52,27.83 19.62,27.94 19.98,27.94 20.33,27.58 20.33,27.22 20.59,26.97 21.35,26.97 21.7,27.33 22.87,27.33 23.02,27.48 23.02,28.14 22.67,28.49 21.55,28.49 21.25,28.8 21.25,28.85 20.43,28.85 20.2,28.62 19.54,28.62 19.52,28.65 19.01,28.65 18.76,28.9 18.76,30.73 18.6,30.88 18.25,30.88
GND on TOP: 8.65,15.34 34.91,15.34 35.32,15.74 37.86,15.74 38.06,15.54 38.06,6.9 37.45,6.29 8.49,6.29 7.63,7.16 7.63,14.32
GND on BOTTOM: -4.51,-0.51 -4.51,52.47 -0.8,56.18 65.75,56.18 76.01,45.92 76.01,0.96 72.76,-2.29 -2.73,-2.29 ; 1 cut-out
VCC_3V3 on TOP: 41.16,33.52 43.95,33.52 44.87,32.61 44.87,32.3 44.97,32.2 45.73,32.2 45.83,32.3 45.83,34.9 46.04,35.1 46.04,35.86 45.88,36.01 43.6,36.01 43.45,35.86 43.45,35.25 44.16,35.25 44.26,35.15 44.26,34.29 44.05,34.08 41.82,34.08 41.21,34.69 41.21,36.01 41.06,36.17 40.65,36.17 40.55,36.06 40.55,34.13
VCC_3V3 on TOP: 19.06,27.68 19.72,27.68 19.92,27.48 19.92,26.97 20.23,26.67 21.45,26.67 21.7,26.92 22.62,26.92 22.72,26.82 22.72,25.95 22.92,25.75 22.92,25.34 22.77,25.19 20.74,25.19 20.48,25.45 19.72,25.45 19.06,26.11
VCC_5V on TOP: 24.9,25.55 24.9,26.31 25.11,26.51 25.87,26.51 25.97,26.41 25.97,23.62 25.82,23.47 25.82,22.75 25.51,22.45 25.06,22.45 24.65,22.04 23.07,22.04 23.07,22.3 23.13,22.35 24.34,22.35 24.85,22.86 24.85,25.5
VCC_5V on TOP: 18.4,36.47 27.75,36.47 27.95,36.27 27.95,31.8 27.6,31.44 22.82,31.44 21.86,32.41 21.86,33.02 21.25,33.63 20.33,33.63 20.13,33.42 20.13,32.81 20.18,32.76 21.14,32.76 21.5,32.41 21.5,31.9 21.4,31.8 20.33,31.8 20.18,31.64 20.18,30.73 20.48,30.42 22.67,30.42 22.92,30.17 22.92,29.26 22.72,29.05 21.45,29.05 21.3,29.21 20.28,29.21 19.92,28.85 19.06,28.85 19.01,28.9 19.01,31.69 18.96,31.75 18.96,32.76 18.1,33.63 18.1,36.17
VCC_5V on TOP: 32.22,18.89 33.74,18.89 33.84,18.99 35.16,18.99 35.72,18.44 36.84,18.44 36.89,18.49 36.89,20.42 36.59,20.72 32.27,20.72 32.02,20.47 32.02,19.1
VCC_IN on TOP: 10.22,43.28 10.37,43.12 12.1,43.12 12.25,42.97 12.25,41.45 12.51,41.19 15.35,41.19 15.45,41.09 15.45,40.48 15.3,40.33 12.56,40.33 12.36,40.13 12.36,35.05 12.05,34.74 11.24,34.74 11.03,34.95 11.03,35.81 10.32,36.52 10.22,36.52 10.12,36.62 10.12,41.65 9.71,42.06 9.71,42.46 9.43,42.74 9.46,42.77 9.46,43.02 9.71,43.28
VCC_IN on BOTTOM: 7.17,19.25 7.17,2.08 62.19,2.08 62.19,19.25
SAMPLE_CURRENT on TOP: 38.42,15.74 38.42,7.06 39.08,6.4 55.59,6.4 56.35,7.16 56.35,11.98 57.21,12.85 61.02,12.85 61.78,13.61 61.78,18.08 59.85,20.01 43.75,20.01 42.99,19.25 42.99,16.51 42.63,16.15 38.82,16.15
N17161105 on TOP: 24.85,44.09 24.85,42.52 23.79,41.45 22.16,41.45 21.86,41.14 21.86,40.38 21.5,40.03 19.11,40.03 18.91,39.82 18.91,38.55 19.47,37.99 27.54,37.99 27.8,38.25 27.8,43.84 27.34,44.29 25.06,44.29

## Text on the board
Ref Des/Silkscreen Top: GND | TMS | TCLK | COULOMETER_BOARD_V1.1 | 2021/02/02 | IN | OUT
NCLEGEND-1-2: FIGURE | FINISHED_SIZE | 10.0 | 36.0 | 37.012 | 40.0 | 79.0 | 91.0 | 102.358 | 64.0x25.0 | ROTATION | - | 179.977 | 0.000 | DRILL CHART: TOP to BOTTOM | ALL UNITS ARE IN MILS | TOLERANCE_DRILL | +10.0/-0.0 | +0.0/-0.0 | +3.0/-3.0 | PLATED | QTY | 121 | 6 | 8 | 4 | 2
